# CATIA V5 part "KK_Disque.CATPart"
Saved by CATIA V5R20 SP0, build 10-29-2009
Part number: disque
Bounding box of the stored display mesh (mm): x -75 to 75, y -75 to 75, z 0 to 2.5
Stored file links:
  G:\Khaled_CFAO_2011\ST2M\ST2M_GR2\tcorbin\Khaled\CAD_ThinkMOTION\KK_Disque.CATPart
  F:\Thinkmotionperso\assemblage robot\ass_skl_robot.CATProduct
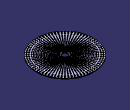
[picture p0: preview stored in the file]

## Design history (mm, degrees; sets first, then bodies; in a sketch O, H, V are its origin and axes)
External parameters (linked from other documents)
  `External.diametre perçage disque_arbre_avbras` = 15 mm
Body1 (main body)
  Sketch1 on xy-plane, origin (0, 0, 0), H (1, 0, 0), V (0, 1, 0)
    circle A1 centre (0, 0) radius 75
    radius A1 = 75
  Pad1: profile Sketch1, direction (0, 0, 1), length 2
  Sketch2 on end face of Pad1, origin (0, 0, 2), H (1, 0, 0), V (0, 1, 0)
    point P1 (0, 0)
  Hole1: placed by Sketch2, at (0, 0, 2) direction (0, 0, -1), diameter 15 {= `External.diametre perçage disque_arbre_avbras`}, through (limit type 3)
  Sketch3 on end face of Pad1, origin (0, 0, 2), H (1, 0, 0), V (0, 1, 0)
    circle A1 centre (0, 71.3096) radius 1.4653
    point P1 (0, 71.3096)
    point P2 (0, 69.8443)
    coincidence: P1 V, A1 P2, P2 V
  Pad2: profile Sketch3, direction (0, 0, 1), length 0.5
  CircPattern1: of Pad2, instances 72, angular step 5, axis from end face of Pad1
  Sketch4 on end face of Pad1, origin (0, 0, 2), H (1, 0, 0), V (0, 1, 0)
    circle A1 centre (0, 61.7819) radius 0.9
    point P1 (0, 61.7819)
    point P2 (0, 60.8819)
    circle A2 centre (0, 58.7819) radius 0.9
    point P3 (0, 58.7819)
    point P4 (0, 61.8729)
    circle A3 centre (0, 55.7819) radius 0.9
    point P5 (0, 55.7819)
    point P6 (0, 51.8819)
    circle A4 centre (0, 52.7819) radius 0.9
    point P7 (0, 52.7819)
    circle A5 centre (0, 49.7819) radius 0.9
    point P8 (0, 49.7819)
    point P9 (0, 48.8819)
    circle A6 centre (0, 46.7819) radius 0.9
    point P10 (0, 46.7819)
    point P11 (0, 45.8819)
    circle A7 centre (0, 43.7819) radius 0.9
    point P12 (0, 43.7819)
    circle A8 centre (0, 40.7819) radius 0.9
    point P13 (0, 40.7819)
    circle A9 centre (0, 37.7819) radius 0.9
    point P14 (0, 37.7819)
    point P15 (0, 36.8819)
    circle A10 centre (0, 31.7819) radius 0.8961
    point P16 (0, 31.7819)
    point P17 (0, 30.8858)
    circle A11 centre (0, 28.7819) radius 0.9
    point P18 (0, 28.7819)
    point P19 (0, 27.8819)
    circle A12 centre (0, 25.7819) radius 0.9
    point P20 (0, 25.7819)
    point P21 (0, 24.8819)
    circle A13 centre (0, 22.7819) radius 0.9
    point P22 (0, 22.7819)
    circle A14 centre (0, 19.7819) radius 0.9
    point P23 (0, 19.7819)
    point P24 (0, 18.8819)
    circle A15 centre (0, 16.7819) radius 0.9
    point P25 (0, 16.7819)
    circle A16 centre (0, 13.7819) radius 0.9
    point P26 (0, 13.7819)
    point P27 (0, 12.8819)
    circle A17 centre (0, 10.7819) radius 0.9
    point P28 (0, 10.7819)
    circle A18 centre (0, 34.7819) radius 0.9
    point P29 (0, 34.7819)
    circle A19 centre (0, 66.7621) radius 1.25
    point P30 (0, 66.7621)
    radius A1 = 0.9
    radius A2 = 0.9
    radius A3 = 0.9
    distance P3 P1 = 3
    distance P3 P5 = 3
    radius A4 = 0.9
    distance P7 P5 = 3
    radius A5 = 0.9
    distance P8 P7 = 3
    radius A6 = 0.9
    distance P10 P8 = 3
    radius A7 = 0.9
    distance P12 P10 = 3
    radius A8 = 0.9
    distance P13 P12 = 3
    radius A9 = 0.9
    distance P14 P13 = 3
    radius A11 = 0.9
    distance P18 P16 = 3
    radius A12 = 0.9
    distance P18 P20 = 3
    radius A13 = 0.9
    distance P22 P20 = 3
    radius A14 = 0.9
    distance P23 P22 = 3
    radius A15 = 0.9
    distance P25 P23 = 3
    distance P27 A16 = 1.8
    distance P26 P25 = 3
    radius A17 = 0.9
    distance P28 P26 = 3
    radius A18 = 0.9
    distance P29 P14 = 3
    distance P16 P29 = 3
    radius A19 = 1.25
    coincidence: P1 V, A1 P2, P2 V, P3 V, P5 V, A4 P6, P7 V, P8 V, A5 P9, P9 V, P10 V, A6 P11, P11 V, P12 V, P13 V, P14 V, A9 P15, P15 V, P16 V, A10 P17, P17 V, P18 V, A11 P19, P19 V, P20 V, A12 P21, P21 V, P22 V, P23 V, A14 P24, P24 V, P25 V, P26 V, A16 P27, P27 V, P28 V, P29 V, P30 V
  Pad3: profile Sketch4, direction (0, 0, 1), length 0.5
  CircPattern2: of the body so far, instances 72, angular step 5, axis from end face of Pad1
